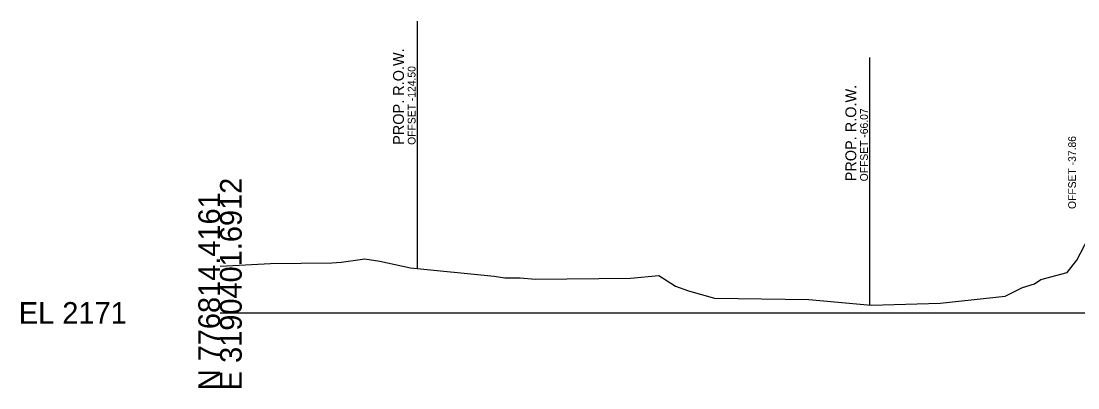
# Model space of a CAD drawing. Extents: x -26 to 303, y -25 to 5046.
# Drawn here: x -25.7 to 110.8, y 1990.3 to 2037.7 of the extents above; entities that cross this region are included whole.
import ezdxf

# ---------------------------------------------------------------- set-up
doc = ezdxf.new("R2010")
doc.units = 0
for name, color, linetype in [('DESIGN - ROW - Right-of-Way and Easement Labels', 7, 'Continuous'), ('DESIGN - ROW - Right-of-Way Linework', 7, 'Continuous'), ('DESIGN - SHEET - Light Grid', 7, 'Continuous'), ('DESIGN - TYPICAL - Slope Tie Text', 7, 'Continuous'), ('SURVEY - GROUND - Top of Ground', 7, 'Continuous')]:
    doc.layers.add(name, color=color, linetype=linetype)

msp = doc.modelspace()

# ---------------------------------------------------------------- linework, layer by layer
at = {"layer": 'DESIGN - ROW - Right-of-Way Linework'}
for p, q in [((25.5, 2005.74), (25.5, 2037.74)), ((83.93, 2001.02), (83.93, 2033.02))]:
    msp.add_line(p, q, dxfattribs=at)
at = {"layer": 'DESIGN - SHEET - Light Grid'}
msp.add_line((0, 2000), (150, 2000), dxfattribs=at)
at = {"layer": 'SURVEY - GROUND - Top of Ground'}
msp.add_lwpolyline([(0, 2006.06), (6.51, 2006.41), (14.46, 2006.46), (15.66, 2006.56), (18.11, 2006.91), (18.71, 2007.01), (20.65, 2006.7), (24.62, 2005.83), (35.39, 2004.77), (36.78, 2004.56), (37.72, 2004.52), (38.77, 2004.52), (40.71, 2004.36), (53.01, 2004.49), (56.7, 2004.86), (58.23, 2003.84), (58.84, 2003.46), (60.49, 2002.87), (63.88, 2001.9), (76.05, 2001.73), (84.12, 2001.01), (93.01, 2001.25), (101.4, 2002.18), (103.64, 2003.31), (105.19, 2003.78), (106.03, 2004.32), (109.43, 2005.22), (110.66, 2006.82), (112.15, 2009.64)], dxfattribs=at)

# ---------------------------------------------------------------- texts
at = {"layer": 'DESIGN - ROW - Right-of-Way and Easement Labels'}
for s, height, p in [('PROP. R.O.W.', 1.4, (23.75, 2021.74)), ('OFFSET -124.50', 1, (25.25, 2021.74)), ('PROP. R.O.W.', 1.4, (82.18, 2017.02)), ('OFFSET -66.07', 1, (83.68, 2017.02))]:
    msp.add_text(s, height=height, rotation=90, dxfattribs=at).set_placement(p)
at = {"layer": 'DESIGN - SHEET - Light Grid'}
for s, p in [('E 3190401.6912', (2.8, 1990)), ('N 776814.4161', (0, 1990))]:
    msp.add_text(s, height=2.8, rotation=90, dxfattribs=at).set_placement(p)
msp.add_text('EL 2171', height=2.8, dxfattribs=at).set_placement((-26, 1998.6))
at = {"layer": 'DESIGN - TYPICAL - Slope Tie Text'}
msp.add_text('OFFSET -37.86', height=1, rotation=90, dxfattribs=at).set_placement((110.56, 2013.44))

doc.saveas('drawing.dxf')
